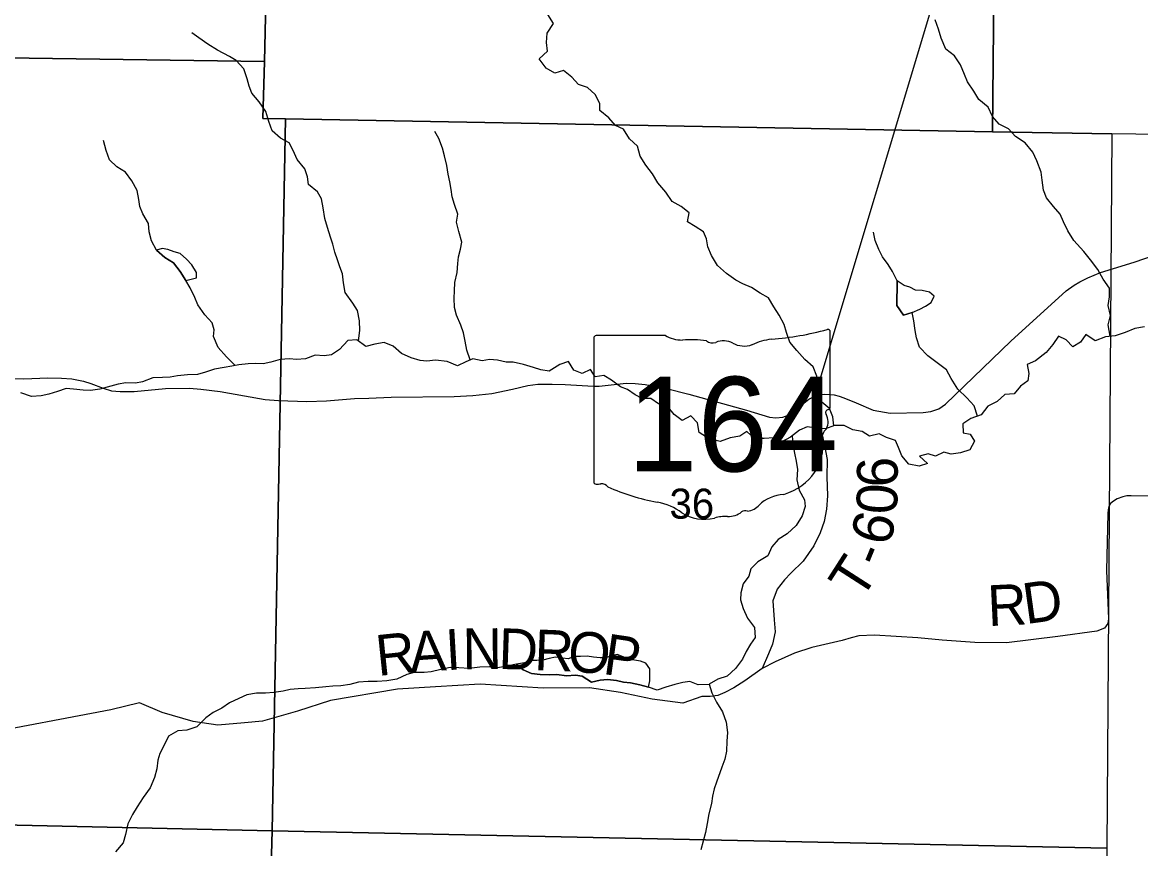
# Model space of a CAD drawing. Extents: x -20.5 to 34, y -66 to 23.9.
# Drawn here: x 5.573 to 7.132, y 16.344 to 17.496 of the extents above; entities that cross this region are included whole.
import ezdxf

# ---------------------------------------------------------------- set-up
doc = ezdxf.new("R2010")
doc.units = 0
for name, color, linetype in [('GM_X_County_Text', 7, 'Continuous'), ('GM_X_Minor_Lake', 7, 'Continuous'), ('GM_X_Minor_River', 7, 'Continuous'), ('GM_X_Minor_River_Text', 7, 'Continuous'), ('GM_X_Section_Text', 7, 'Continuous'), ('GM_X_Township_Road', 7, 'Continuous'), ('GM_X_Township_Text', 7, 'Continuous'), ('GM_X_Unincorporated', 7, 'Continuous'), ('GM_X_Unincorporated_Location', 7, 'Continuous')]:
    doc.layers.add(name, color=color, linetype=linetype)

msp = doc.modelspace()

# ---------------------------------------------------------------- linework, layer by layer
at = {"layer": 'GM_X_County_Text'}
msp.add_line((6.9226, 17.7886), (6.6781, 16.9745), dxfattribs=at)
for points in [[(6.6781, 16.9745), (6.6798, 16.9597), (6.6872, 16.9248), (6.6914, 16.9056), (6.6951, 16.8862), (6.6948, 16.8623), (6.6954, 16.8358), (6.6942, 16.8173), (6.6908, 16.8001), (6.6852, 16.7843), (6.6766, 16.7659), (6.6615, 16.7446), (6.6446, 16.7279), (6.6358, 16.7188), (6.6253, 16.7055), (6.6192, 16.6892), (6.6212, 16.663), (6.6224, 16.646), (6.619, 16.6291), (6.6132, 16.6153), (6.6047, 16.5949)], [(7.1972, 16.835), (7.119, 16.8357), (7.1132, 16.8356), (7.1076, 16.8343), (7.0995, 16.8314), (7.0944, 16.8284), (7.0905, 16.8249), (7.0878, 16.821), (7.0872, 16.816), (7.0867, 16.8111), (7.0846, 16.7314), (7.0875, 16.6641), (7.0864, 16.6578), (7.082, 16.6512), (7.0715, 16.6471), (7.0168, 16.6397), (6.9451, 16.6308), (6.9013, 16.6313), (6.8557, 16.6343), (6.8216, 16.6377), (6.7612, 16.6415), (6.7395, 16.6406), (6.7284, 16.6377), (6.716, 16.634), (6.6736, 16.6243), (6.6495, 16.6165), (6.6227, 16.6041), (6.6047, 16.5949)], [(6.6047, 16.5949), (6.5803, 16.5777), (6.565, 16.568), (6.5526, 16.5614), (6.5425, 16.5575), (6.532, 16.5561), (6.5203, 16.556), (6.494, 16.5465), (6.4509, 16.5523), (6.407, 16.5616), (6.3635, 16.5679), (6.2992, 16.5675), (6.2112, 16.5732), (6.1489, 16.5695), (6.0957, 16.566), (6.0025, 16.5502), (5.9564, 16.5355), (5.9073, 16.5218), (5.8822, 16.5193), (5.8454, 16.5162), (5.8107, 16.5211), (5.7678, 16.5335), (5.7359, 16.5472), (5.6962, 16.5372), (5.5091, 16.5021)]]:
    msp.add_lwpolyline(points, dxfattribs=at)
at = {"layer": 'GM_X_Minor_Lake'}
for points in [[(4.9118, 18.4742), (5.9332, 18.4574), (5.9313, 18.3709), (5.9103, 17.4412), (4.9246, 17.4548), (4.898, 17.4556)], [(6.9356, 18.3607), (6.9259, 17.3432), (5.9397, 17.3613), (5.9082, 17.3615), (5.9103, 17.4412), (5.9313, 18.3709)], [(7.9409, 18.3387), (7.9284, 17.3287), (7.0924, 17.3404), (6.9259, 17.3432), (6.9356, 18.3607)], [(4.9246, 17.4548), (5.9103, 17.4412), (5.9082, 17.3615), (5.9397, 17.3613), (5.9209, 16.3687), (4.8948, 16.3916)], [(5.9397, 17.3613), (6.9259, 17.3432), (7.0924, 17.3404), (7.0853, 16.3445), (5.9209, 16.3687)], [(4.8948, 16.3916), (5.9209, 16.3687), (5.8926, 15.3531), (4.8742, 15.38)], [(7.0853, 16.3445), (7.0733, 15.3334), (5.8926, 15.3531), (5.9209, 16.3687)]]:
    msp.add_lwpolyline(points, close=True, dxfattribs=at)
at = {"layer": 'GM_X_Minor_River'}
for points in [[(5.8006, 17.1358), (5.8157, 17.1394), (5.8156, 17.147), (5.809, 17.1575), (5.8013, 17.1657), (5.7929, 17.1732), (5.7845, 17.1757), (5.7757, 17.179), (5.7674, 17.1804), (5.7595, 17.178)], [(5.7595, 17.178), (5.7714, 17.1679), (5.7836, 17.1602), (5.7929, 17.1485), (5.8006, 17.1358)], [(6.7928, 17.1353), (6.793, 17.1239), (6.7924, 17.111), (6.7922, 17.1008), (6.8015, 17.0876), (6.8135, 17.0912)], [(6.8135, 17.0912), (6.8244, 17.0956), (6.8323, 17.0999), (6.8402, 17.1049), (6.8446, 17.1141), (6.8381, 17.1193), (6.8278, 17.1218), (6.8183, 17.1224), (6.8103, 17.1265), (6.8027, 17.129), (6.7928, 17.1353)], [(6.4461, 16.5689), (6.4478, 16.5777), (6.4476, 16.5944), (6.4422, 16.6023), (6.4346, 16.6052), (6.4266, 16.6066), (6.4182, 16.608), (6.4106, 16.6113), (6.4022, 16.6146), (6.394, 16.6125), (6.3864, 16.6098), (6.3785, 16.61), (6.3694, 16.611), (6.3603, 16.6124), (6.3512, 16.6119), (6.3421, 16.6118), (6.3338, 16.6086), (6.3259, 16.6096), (6.3164, 16.6106), (6.3074, 16.609), (6.2987, 16.6066), (6.2904, 16.606), (6.2813, 16.6063), (6.273, 16.6031), (6.2617, 16.6011)], [(6.2617, 16.6011), (6.2713, 16.5932), (6.2827, 16.5881), (6.2948, 16.5868), (6.3073, 16.5862), (6.3179, 16.5864), (6.3316, 16.585), (6.344, 16.5856), (6.3535, 16.5842), (6.3665, 16.5761), (6.3786, 16.5789), (6.3888, 16.5798), (6.4013, 16.5785), (6.4112, 16.576), (6.4206, 16.575), (6.4339, 16.5722), (6.4461, 16.5689)]]:
    msp.add_lwpolyline(points, dxfattribs=at)
at = {"layer": 'GM_X_Minor_River_Text'}
for points in [[(6.7045, 16.9333), (6.703, 16.9458), (6.6982, 16.9575), (6.6856, 16.9679), (6.6835, 16.9785), (6.6818, 16.9917), (6.6809, 17.0023), (6.6758, 17.0155), (6.6639, 17.0256), (6.6527, 17.038), (6.6431, 17.05), (6.6384, 17.0632), (6.6352, 17.0745), (6.6282, 17.0873), (6.6208, 17.0993), (6.6134, 17.1117), (6.6016, 17.118), (6.5897, 17.1258), (6.5775, 17.1313), (6.5676, 17.1364), (6.5546, 17.1457), (6.542, 17.1569), (6.5338, 17.1704), (6.5287, 17.1829), (6.527, 17.1939), (6.5227, 17.2037), (6.5112, 17.2111), (6.5002, 17.2177), (6.5026, 17.2303), (6.4915, 17.2388), (6.4789, 17.2459), (6.47, 17.259), (6.4589, 17.2717), (6.4515, 17.2845), (6.4422, 17.2965), (6.4341, 17.3093), (6.4308, 17.3229), (6.4193, 17.3333), (6.4112, 17.3465), (6.4001, 17.3516), (6.3905, 17.3625), (6.3782, 17.3729), (6.3781, 17.3824), (6.3715, 17.3948), (6.3607, 17.4049), (6.3485, 17.4089), (6.3389, 17.419), (6.3274, 17.4287), (6.3154, 17.4247), (6.3032, 17.4317), (6.2935, 17.4448), (6.3051, 17.4556), (6.3037, 17.4677), (6.3047, 17.4807), (6.3132, 17.4941), (6.3054, 17.5065)], [(7.0898, 17.058), (7.087, 17.0741), (7.0905, 17.0871), (7.0869, 17.1007), (7.089, 17.1128), (7.0888, 17.125), (7.0803, 17.1377), (7.0725, 17.1513), (7.0625, 17.1648), (7.0532, 17.1764), (7.0394, 17.1914), (7.0309, 17.2049), (7.0246, 17.2177), (7.0199, 17.2283), (7.011, 17.2391), (7.001, 17.2511), (6.9971, 17.2617), (6.995, 17.2757), (6.9937, 17.287), (6.9878, 17.3025), (6.9819, 17.3145), (6.9711, 17.3277), (6.9577, 17.3366), (6.9481, 17.347), (6.9351, 17.3537), (6.9259, 17.3645), (6.9196, 17.3773), (6.9066, 17.3881), (6.8996, 17.3998), (6.8911, 17.4129), (6.8868, 17.4227), (6.8809, 17.4363), (6.8728, 17.4491), (6.8605, 17.4584), (6.8542, 17.4735), (6.8502, 17.4863), (6.8459, 17.4991)], [(6.0412, 17.0518), (6.0435, 17.0659), (6.0429, 17.0795), (6.04, 17.0939), (6.0334, 17.104), (6.023, 17.1191), (6.0205, 17.1323), (6.0192, 17.1452), (6.0153, 17.155), (6.0121, 17.1648), (6.0085, 17.1753), (6.0057, 17.1863), (6.0025, 17.1961), (5.9982, 17.2097), (5.9946, 17.2222), (5.9921, 17.2369), (5.99, 17.2494), (5.9842, 17.2592), (5.9719, 17.2696), (5.9702, 17.2802), (5.9666, 17.2912), (5.9558, 17.3043), (5.9503, 17.3171), (5.9449, 17.3276), (5.9327, 17.3343), (5.9212, 17.3443), (5.9164, 17.3572), (5.9121, 17.3715), (5.9028, 17.385), (5.8927, 17.397), (5.8888, 17.4068), (5.886, 17.417), (5.8816, 17.431), (5.8709, 17.4426), (5.8613, 17.4481), (5.8449, 17.4566), (5.8312, 17.4651), (5.8185, 17.474), (5.809, 17.4811)], [(5.8693, 17.0173), (5.8575, 17.0293), (5.8459, 17.0424), (5.8393, 17.0575), (5.8399, 17.067), (5.8375, 17.0768), (5.8271, 17.088), (5.8174, 17.1019), (5.8131, 17.1121), (5.8068, 17.1256), (5.8006, 17.1358), (5.7929, 17.1485), (5.7836, 17.1602), (5.7714, 17.1679), (5.7595, 17.178), (5.7525, 17.1912), (5.7496, 17.2036), (5.7487, 17.2154), (5.7406, 17.2285), (5.7366, 17.2387), (5.7349, 17.2489), (5.7329, 17.2614), (5.7255, 17.2746), (5.7166, 17.2866), (5.7044, 17.294), (5.694, 17.3041), (5.6896, 17.3169), (5.6856, 17.3309)], [(6.1973, 17.025), (6.1926, 17.0386), (6.1901, 17.051), (6.1881, 17.0628), (6.1841, 17.0737), (6.1782, 17.0873), (6.1754, 17.0982), (6.1749, 17.1111), (6.1755, 17.1214), (6.176, 17.1331), (6.1789, 17.1468), (6.1798, 17.1594), (6.1808, 17.1689), (6.1837, 17.1795), (6.1854, 17.1894), (6.1814, 17.2042), (6.1782, 17.217), (6.1799, 17.228), (6.1751, 17.2416), (6.1719, 17.2526), (6.1707, 17.2628), (6.169, 17.2734), (6.1665, 17.284), (6.1645, 17.2961), (6.1612, 17.3097), (6.1588, 17.3203), (6.1533, 17.3338), (6.1478, 17.3436)], [(6.9047, 16.9467), (6.9002, 16.9613), (6.8899, 16.9721), (6.8772, 16.9844), (6.8679, 16.9991), (6.8616, 17.0111), (6.8486, 17.0212), (6.8356, 17.0309), (6.8241, 17.0428), (6.8197, 17.056), (6.8177, 17.0659), (6.816, 17.0795), (6.8135, 17.0912), (6.8015, 17.0876), (6.7922, 17.1008), (6.7924, 17.111), (6.793, 17.1239), (6.7928, 17.1353), (6.7862, 17.1481), (6.7803, 17.1582), (6.7722, 17.1687), (6.7671, 17.1789), (6.762, 17.1917), (6.7596, 17.2031)], [(7.1377, 17.0711), (7.1241, 17.069), (7.1106, 17.0635), (7.097, 17.0587), (7.0834, 17.0574), (7.0688, 17.0515), (7.0561, 17.0604), (7.0487, 17.0496), (7.0379, 17.0434), (7.0286, 17.0531), (7.018, 17.0583)], [(7.018, 17.0583), (7.0098, 17.0464), (7.0005, 17.0356), (6.9859, 17.024), (6.9739, 17.0189), (6.9764, 17.0061), (6.975, 16.9958), (6.9649, 16.9884), (6.956, 16.9777), (6.9431, 16.9767), (6.9323, 16.9671), (6.9192, 16.9604), (6.9099, 16.9485), (6.8956, 16.9434), (6.8844, 16.936), (6.8849, 16.9235), (6.8948, 16.9217), (6.9006, 16.912), (6.894, 16.8997), (6.8812, 16.8957), (6.868, 16.8936), (6.8577, 16.8965), (6.8461, 16.891), (6.8362, 16.8943), (6.8241, 16.8911), (6.8352, 16.8806), (6.8236, 16.877), (6.8092, 16.8798), (6.7991, 16.8915), (6.7944, 16.9031), (6.7905, 16.913), (6.7779, 16.9169), (6.7676, 16.9221), (6.7541, 16.9189), (6.7441, 16.9255), (6.7309, 16.9276), (6.7187, 16.9339), (6.7054, 16.9337), (6.693, 16.9289), (6.6801, 16.9299), (6.6672, 16.9316), (6.6567, 16.9272), (6.644, 16.9176), (6.6308, 16.9105), (6.6209, 16.9165), (6.6073, 16.9155), (6.5937, 16.9157), (6.5829, 16.9254), (6.5732, 16.9188), (6.56, 16.9163), (6.5461, 16.9115), (6.5305, 16.9151), (6.5167, 16.924), (6.5143, 16.9372), (6.505, 16.9473), (6.4927, 16.9407), (6.4819, 16.9489), (6.4738, 16.9586), (6.4601, 16.9641), (6.449, 16.9715), (6.4373, 16.9713), (6.4274, 16.9765), (6.4167, 16.9839), (6.4068, 16.9876), (6.3942, 16.9969), (6.3835, 17.0035), (6.3714, 17.0014), (6.3648, 17.0116), (6.3532, 17.0061), (6.3417, 17.0109), (6.3344, 17.0229), (6.3223, 17.0189), (6.3073, 17.0092), (6.2956, 17.0113), (6.2853, 17.0146), (6.2716, 17.0185), (6.2572, 17.0221), (6.2474, 17.0219), (6.2352, 17.0248), (6.2242, 17.0258), (6.214, 17.0237), (6.2011, 17.0265), (6.1913, 17.0226), (6.1793, 17.0167), (6.1652, 17.023), (6.1486, 17.0246), (6.1368, 17.0233), (6.1274, 17.0243), (6.1148, 17.0279), (6.1015, 17.0338), (6.09, 17.0442), (6.0774, 17.0493), (6.0642, 17.0472), (6.0518, 17.044), (6.0391, 17.0533), (6.0267, 17.0523), (6.0151, 17.0397), (6.0039, 17.0323), (5.9937, 17.0306), (5.9808, 17.0315), (5.9677, 17.0264)], [(5.9677, 17.0264), (5.9548, 17.0255), (5.9453, 17.0265), (5.9321, 17.0259), (5.9193, 17.0219), (5.9083, 17.0194), (5.8974, 17.02), (5.8875, 17.0195), (5.8747, 17.0182), (5.8649, 17.0165), (5.8539, 17.0144), (5.8404, 17.012), (5.8279, 17.008), (5.817, 17.0048), (5.803, 17.0042), (5.789, 17.0028), (5.7788, 17.0012), (5.7679, 17.0006), (5.7546, 17), (5.74, 16.9945), (5.7302, 16.9928), (5.7169, 16.993), (5.7063, 16.9913), (5.6807, 16.9845), (5.6675, 16.9824), (5.6573, 16.983), (5.644, 16.9843), (5.6338, 16.9853), (5.6214, 16.9809), (5.6097, 16.9773), (5.5987, 16.9749), (5.5851, 16.9743), (5.5703, 16.9794)], [(6.6463, 16.9193), (6.6472, 16.9081), (6.6496, 16.8949), (6.6517, 16.8839), (6.6537, 16.8722), (6.6528, 16.8581), (6.6561, 16.8434), (6.6635, 16.8302), (6.6644, 16.8208), (6.6604, 16.8078), (6.6519, 16.7944), (6.6392, 16.7828), (6.6269, 16.7747), (6.6179, 16.7647), (6.6124, 16.7521), (6.5986, 16.7435), (6.5885, 16.7339), (6.586, 16.7236), (6.5782, 16.7128), (6.5746, 16.7003), (6.5744, 16.6908), (6.578, 16.6787), (6.5842, 16.6651), (6.5939, 16.652), (6.5949, 16.6384), (6.5882, 16.6288), (6.5823, 16.6188), (6.5772, 16.6081), (6.5671, 16.5951), (6.5556, 16.5843), (6.5428, 16.5803), (6.5304, 16.5733), (6.5344, 16.5612), (6.5406, 16.548), (6.5491, 16.5348), (6.5543, 16.5201), (6.556, 16.5057), (6.5554, 16.4936), (6.5549, 16.4799), (6.5524, 16.4685), (6.548, 16.4574), (6.5408, 16.4368), (6.5375, 16.4273), (6.535, 16.417), (6.5337, 16.4067), (6.5301, 16.3926), (6.5276, 16.3789), (6.5256, 16.3664), (6.5223, 16.3542), (6.5187, 16.3424)], [(6.5306, 16.5725), (6.5153, 16.5723), (6.5035, 16.577), (6.4937, 16.5754), (6.4827, 16.5729), (6.4703, 16.5689), (6.4579, 16.5646), (6.4461, 16.5689), (6.4339, 16.5722), (6.4206, 16.575), (6.4112, 16.576), (6.4013, 16.5785), (6.3888, 16.5798), (6.3786, 16.5789), (6.3665, 16.5761), (6.3535, 16.5842), (6.344, 16.5856), (6.3316, 16.585), (6.3179, 16.5864), (6.3073, 16.5862), (6.2948, 16.5868), (6.2827, 16.5881), (6.2713, 16.5932), (6.2617, 16.6011), (6.2481, 16.5982), (6.2357, 16.5961), (6.2239, 16.5975), (6.2107, 16.5969), (6.1956, 16.5951), (6.1816, 16.5957), (6.1691, 16.5966), (6.1562, 16.5934), (6.143, 16.5902), (6.1332, 16.5896), (6.1192, 16.5894), (6.109, 16.5866), (6.0951, 16.5803), (6.0808, 16.5778), (6.0676, 16.5769), (6.0547, 16.5767), (6.0415, 16.5761), (6.0294, 16.5729), (6.0166, 16.5708), (6.0056, 16.5706), (5.9958, 16.5693), (5.9814, 16.568), (5.9671, 16.567), (5.9572, 16.5668), (5.9463, 16.5655), (5.9365, 16.5635), (5.9233, 16.5614), (5.9119, 16.5608), (5.8991, 16.5606), (5.8858, 16.5582), (5.8746, 16.5534), (5.8614, 16.5472), (5.8509, 16.5398), (5.8389, 16.5336), (5.8284, 16.5262), (5.8158, 16.5135), (5.8022, 16.5091), (5.7894, 16.5081), (5.7766, 16.5007), (5.7707, 16.4893), (5.7641, 16.4766), (5.7616, 16.4671), (5.7603, 16.4553), (5.7567, 16.4431), (5.7508, 16.4286), (5.7412, 16.4152), (5.7327, 16.4022), (5.7264, 16.3915), (5.7198, 16.3785), (5.7166, 16.3636), (5.713, 16.3518), (5.7026, 16.3395)]]:
    msp.add_lwpolyline(points, dxfattribs=at)
at = {"layer": 'GM_X_Township_Road'}
msp.add_lwpolyline([(5.5301, 16.9996), (5.5745, 16.9987), (5.608, 17), (5.6273, 16.9998), (5.6415, 16.9985), (5.6579, 16.9955), (5.6679, 16.992), (5.6855, 16.9855), (5.697, 16.9822), (5.7091, 16.9812), (5.7285, 16.9813), (5.7721, 16.9852), (5.8058, 16.9857), (5.8213, 16.9844), (5.8486, 16.9813), (5.8826, 16.975), (5.9113, 16.9701), (5.9299, 16.9684), (5.9694, 16.9673), (5.9967, 16.968), (6.036, 16.9711), (6.0557, 16.9717), (6.0868, 16.9733), (6.175, 16.9741), (6.2007, 16.9753), (6.2273, 16.9784), (6.2562, 16.9845), (6.2775, 16.9892), (6.2916, 16.9914), (6.3116, 16.9914), (6.3299, 16.991), (6.3536, 16.9892), (6.3691, 16.9884), (6.3772, 16.9883), (6.415, 16.9929), (6.4274, 16.9924), (6.4413, 16.991), (6.4711, 16.9853), (6.5024, 16.9774), (6.5825, 16.955), (6.6148, 16.9453), (6.6235, 16.9444), (6.6332, 16.9453), (6.6423, 16.9485), (6.6694, 16.9706), (6.6781, 16.9745), (6.6848, 16.9764), (6.691, 16.9773), (6.6998, 16.977), (6.705, 16.9764), (6.7117, 16.9745), (6.7183, 16.9724), (6.7354, 16.9653), (6.7595, 16.9552), (6.7828, 16.951), (6.8289, 16.9516), (6.8399, 16.9531), (6.8509, 16.9571), (6.8603, 16.9636), (6.9512, 17.0511), (7.0285, 17.1215), (7.0396, 17.1294), (7.0476, 17.1341), (7.0585, 17.1396), (7.0763, 17.1469), (7.1233, 17.1611), (7.1531, 17.1714)], dxfattribs=at)
at = {"layer": 'GM_X_Unincorporated'}
for p, q in [((6.6993, 16.9594), (6.6993, 17.0641)), ((6.3697, 17.0557), (6.3697, 16.8556)), ((6.4695, 17.0591), (6.373, 17.0591)), ((6.6993, 16.9594), (6.6993, 16.9594))]:
    msp.add_line(p, q, dxfattribs=at)
for centre, major_axis, start_param, end_param in [((6.5819, 17.332), (0.3495, 0), 4.814394, 5.042369), ((6.6957, 17.0645), (0.00367, 0), 6.141152, 7.989035), ((6.3735, 17.0561), (0.00382, 0), 1.712693, 3.28349), ((6.4925, 17.0824), (0.037, 0), 4.042523, 4.731795), ((6.5048, 16.9468), (0.133, 0), 1.404758, 1.657858), ((6.5349, 17.0572), (0.0107, 0), 3.836095, 5.185415), ((6.5506, 17.034), (0.0222, 0), 0.950623, 2.079405), ((6.5793, 17.0658), (0.0267, 0), 4.081561, 5.145723), ((6.6265, 16.998), (0.0703, 0), 1.699011, 2.107814), ((6.6985, 16.9517), (0.00568, 0), 1.883978, 3.671073), ((6.6954, 16.959), (0.00393, 0), 5.05454, 6.418171), ((6.6623, 16.9385), (0.0341, 0), 5.934695, 6.695948), ((6.7125, 16.9156), (0.0248, 0), 2.387724, 3.262537), ((6.6015, 16.9023), (0.0874, 0), 5.101752, 6.440018), ((6.3735, 16.8551), (0.00385, 0), 3.00124, 4.508301), ((6.3741, 16.8756), (0.0294, 0), 4.665946, 4.897461), ((6.3801, 16.844), (0.0106, 0), 0.519207, 1.627899), ((6.514, 17.0238), (0.2524, 0), 4.195997, 4.488961), ((6.6384, 16.7994), (0.0479, 0), 1.647645, 2.488434), ((6.4387, 16.7657), (0.079, 0), 0.823519, 1.323587), ((6.5809, 16.8087), (0.00752, 0), 1.147584, 2.315152), ((6.5777, 16.8362), (0.0282, 0), 4.937069, 5.64225), ((6.5241, 16.843), (0.0501, 0), 4.026481, 4.996735), ((6.5531, 16.7739), (0.0412, 0), 1.495662, 1.94098), ((6.5567, 16.8281), (0.0267, 0), 4.691044, 5.507374)]:
    msp.add_ellipse(centre, major_axis=major_axis, ratio=0.8, start_param=start_param, end_param=end_param, dxfattribs=at)

# ---------------------------------------------------------------- texts
at = {"layer": 'GM_X_Section_Text'}
for s, rotation, p in [('6', 90.8275, (6.7939, 16.848)), ('0', 86.8112, (6.7919, 16.8089)), ('6', 76.4375, (6.7821, 16.7641)), ('T', 57.2942, (6.7423, 16.6881)), ('-', 67.6515, (6.7704, 16.7337)), ('R', 2.6999, (6.92, 16.654)), ('D', 7.9356, (6.9722, 16.6567)), ('R', 5.9863, (6.0686, 16.5845)), ('A', 3.7822, (6.1144, 16.5893)), ('I', 3.2647, (6.1642, 16.5926)), ('N', 0.6229, (6.1868, 16.5939)), ('D', 358.0635, (6.2361, 16.5945)), ('R', 357.7377, (6.286, 16.5928)), ('O', 356.0408, (6.3322, 16.591)), ('P', 351.8094, (6.3809, 16.5876))]:
    msp.add_text(s, height=0.0568, rotation=rotation, dxfattribs=at).set_placement(p)
at = {"layer": 'GM_X_Township_Text'}
msp.add_text('36', height=0.04186, rotation=0, dxfattribs=at).set_placement((6.4752, 16.8038))
at = {"layer": 'GM_X_Unincorporated'}
msp.add_text('164', height=0.13184, dxfattribs=at).set_placement((6.4163, 16.8697))
at = {"layer": 'GM_X_Unincorporated_Location'}
for s in ['s', 'r']:
    msp.add_text(s, height=0.000189, dxfattribs=at).set_placement((6.5308, 16.9423))
msp.add_text('164', height=0.000189, rotation=0, dxfattribs=at).set_placement((6.464, 16.9286))

doc.saveas('drawing.dxf')
